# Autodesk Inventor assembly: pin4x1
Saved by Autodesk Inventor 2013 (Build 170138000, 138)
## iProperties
Created: 2021-02
Part Number: pin4x1
Document SubType Name: Assembly
Designer: Fede
Author: Fede
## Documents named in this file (3)
- C:\0000 FEDE\16GB\0000 INTERIOR\DE_TMP_BAS\BAS_DTON - demora conexion al energizar\DTON_MANUAL\img\INVENTOR\BAS_DTON - SIN R\pin4x1.iam
- C:\0000 FEDE\16GB\0000 INTERIOR\DE_TMP_BAS\BAS_DTON - demora conexion al energizar\DTON_MANUAL\img\INVENTOR\BAS_DTON - SIN R\cgrid_1x1_parte2.iam
- C:\0000 FEDE\16GB\0000 INTERIOR\DE_TMP_BAS\BAS_DTON - demora conexion al energizar\DTON_MANUAL\img\INVENTOR\BAS_DTON - SIN R\pin.ipt
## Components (8 placed, 2 different names)
1. cgrid_1x1_parte2:1 [sub-assembly]
2. pin:1
3. cgrid_1x1_parte2:2 [sub-assembly]
4. pin:2
5. cgrid_1x1_parte2:3 [sub-assembly]
6. pin:3
7. cgrid_1x1_parte2:4 [sub-assembly]
8. pin:4
